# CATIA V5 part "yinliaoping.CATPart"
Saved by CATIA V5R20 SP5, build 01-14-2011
Part number: 饮料瓶
Material "DS Light Blue": density 7860 kg/m3, Young's modulus 2e+11 Pa, Poisson ratio 0.266
Bounding box of the stored display mesh (mm): x -25.2 to 25, y -25 to 25, z 0 to 110
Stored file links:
  E:\180211226\yinliaoping.CATPart
  C:\Program Files\Dassault Systemes\B20\intel_a\startup\materials\Catalog.CATMaterial
  C:\Program Files\Dassault Systemes\B20\intel_a\startup\materials\blue_env_512x512.jpg
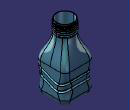
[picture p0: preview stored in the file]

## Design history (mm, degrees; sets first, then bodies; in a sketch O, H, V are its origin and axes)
Set1
  Sketch1 on xy-plane, origin (0, 0, 0), H (1, 0, 0), V (0, 1, 0)
    line L1 (25, 25) -> (25, -25)
    line L2 (25, -25) -> (-25, -25)
    line L3 (-25, -25) -> (-25, 25)
    line L4 (-25, 25) -> (25, 25)
    length L4 = 50
    length L1 = 50
    vertical: L1 V, L3 V
    horizontal: L2 H, L4 H
    equidistance: L1 L3 O, L2 L4 O
  Sketch2 on face of Pad1 from Sketch1.L1, origin (25, 0, 0), H (0, 1, 0), V (0, 0, 1)
    spline S1 through (-40, 20) (-20, 30) (10, 20) (30, 30)
  Extrude1: Element1 Sketch2, Lim1 70, Lim2 0
  MultiSel1: CommonCtxFeats ({extract ExtractElem face of Pad1 from Sketch1.L2}; {extract ExtractElem face of Fillet1}; {extract ExtractElem face of Pad1 from Sketch1.L1}; {extract ExtractElem face of Fillet1}; {extract ExtractElem face of Pad1 from Sketch1.L4}; {extract ExtractElem face of Fillet1}; {extract ExtractElem face of Pad1 from Sketch1.L3}; {extract ExtractElem face of Fillet1})
  Sketch3 on face of Pad1 from Sketch1.L1, origin (25, 0, 0), H (0, 1, 0), V (0, 0, 1)
    spline S1 through (-40, 30) (-20, 40) (10, 30) (30, 40)
  Extrude2: Element1 Sketch3, Lim1 70, Lim2 0
  MultiSel2: CommonCtxFeats ({extract ExtractElem face of Pad1 from Sketch1.L4}; {extract ExtractElem face of Fillet1}; {extract ExtractElem face of Pad1 from Sketch1.L1}; {extract ExtractElem face of Fillet1}; {extract ExtractElem face of Pad1 from Sketch1.L3}; {extract ExtractElem face of Fillet1}; {extract ExtractElem face of Pad1 from Sketch1.L2}; {extract ExtractElem face of Fillet1})
  Join1: Elements ({intersect ToIntersect1 {extract ExtractElem face of Pad1 from Sketch1.L2}, ToIntersect2 Extrude1}; {intersect ToIntersect1 {extract ExtractElem face of Fillet1}, ToIntersect2 Extrude1}; {intersect ToIntersect1 {extract ExtractElem face of Pad1 from Sketch1.L1}, ToIntersect2 Extrude1}; {intersect ToIntersect1 {extract ExtractElem face of Fillet1}, ToIntersect2 Extrude1}; {intersect ToIntersect1 {extract ExtractElem face of Pad1 from Sketch1.L4}, ToIntersect2 Extrude1}; {intersect ToIntersect1 {extract ExtractElem face of Fillet1}, ToIntersect2 Extrude1}; {intersect ToIntersect1 {extract ExtractElem face of Pad1 from Sketch1.L3}, ToIntersect2 Extrude1}; {intersect ToIntersect1 {extract ExtractElem face of Fillet1}, ToIntersect2 Extrude1})
  Join2: Elements ({intersect ToIntersect1 {extract ExtractElem face of Pad1 from Sketch1.L4}, ToIntersect2 Extrude2}; {intersect ToIntersect1 {extract ExtractElem face of Fillet1}, ToIntersect2 Extrude2}; {intersect ToIntersect1 {extract ExtractElem face of Pad1 from Sketch1.L1}, ToIntersect2 Extrude2}; {intersect ToIntersect1 {extract ExtractElem face of Fillet1}, ToIntersect2 Extrude2}; {intersect ToIntersect1 {extract ExtractElem face of Pad1 from Sketch1.L3}, ToIntersect2 Extrude2}; {intersect ToIntersect1 {extract ExtractElem face of Fillet1}, ToIntersect2 Extrude2}; {intersect ToIntersect1 {extract ExtractElem face of Pad1 from Sketch1.L2}, ToIntersect2 Extrude2}; {intersect ToIntersect1 {extract ExtractElem face of Fillet1}, ToIntersect2 Extrude2})
  Plane1: type Normal, Curve Join1, RefPoint vertex [face of MultiSel1 | face of MultiSel1]
  Sketch4 on Plane1, origin (0, -20.5956, 7.0712), H (1, 0, 0), V (0, 0.3247, 0.9458)
    circle A1 centre (25.2218, 22.4128) radius 2
    radius A1 = 2
Body1 (main body), material "DS Light Blue"
  Pad1: profile Sketch1, direction (0, 0, 1), length 50
  Fillet1: on edge [face of Pad1 from Sketch1.L2 | face of Pad1 from Sketch1.L3]; edge [face of Pad1 from Sketch1.L1 | face of Pad1 from Sketch1.L2]; edge [face of Pad1 from Sketch1.L3 | face of Pad1 from Sketch1.L4]; edge [face of Pad1 from Sketch1.L4 | face of Pad1 from Sketch1.L1]
  Fillet2: radius 8, on start face of Pad1
  Plane2: type Offset, RefPlane xy-plane, Offset 90
  Sketch5 on Plane2, origin (0, 0, 90), H (1, 0, 0), V (0, 1, 0)
    circle A1 centre (0, 0) radius 15
    radius A1 = 15
  Pad2: profile Sketch5, direction (0, 0, 1), length 20
  Sketch6 on end face of Pad1, origin (0, 0, 50), H (1, 0, 0), V (0, 1, 0)
    point P1 (25, 0)
    distance P1 V = 25
    coincidence: P1 H
  Sketch7 on start face of Pad2, origin (0, 0, 90), H (1, 0, 0), V (0, -1, 0)
    point P1 (15, 0)
    distance P1 V = 15
    coincidence: P1 H
  Loft1: solid, Sections ({boundary Boundary {extract ExtractElem start face of Pad2}}; {boundary Boundary {extract ExtractElem end face of Pad1}}), StartFace start face of Pad2, EndFace end face of Pad1
  Slot1: profile Sketch4, centre curve Join1
  Plane3: type Normal, Curve Join2, RefPoint vertex [face of MultiSel2 | face of MultiSel2]
  Sketch8 on Plane3, origin (0, -24.5459, 6.218), H (1, 0, 0), V (0, 0.2456, 0.9694)
    circle A1 centre (24.9098, 34.4051) radius 2
    radius A1 = 2
  Slot2: profile Sketch8, centre curve Join2
  Shell1: ExtOffset 0, Face end face of Pad2, IntOffset 1
  Plane4: type Offset, RefPlane Plane2, Offset 2
  Sketch9 on Plane4, origin (0, 0, 92), H (1, 0, 0), V (0, 1, 0)
    point P1 (15, 0)
    distance P1 V = 15
    coincidence: P1 H
  Helix1: Direction Z axis, RefPoint Sketch9, Pitch 3, Height 16, TaperAngle 0
  Point1: type OnCurve, Support Helix1, Length 5
  Line1: type PtDir, RefPoint Sketch9, Direction (1, 0, 0), Start 0, End 5
  Connect1: Curve1 Line1, Point1 vertex of Line1, Tension1 1, Curve2 Helix1, Point2 Point1, Tension2 1
  Point2: type OnCurve, Support Connect1, RefPoint vertex of Helix1, Length 5
  Line2: type PtDir, RefPoint vertex of Helix1, Direction (0, 1, 0), Start 0, End 5
  Connect2: Curve1 Connect1, Point1 Point2, Tension1 1, Curve2 Line2, Point2 vertex of Line2, Tension2 1
  Plane5: type Normal, Curve Connect2
  Sketch10 on Plane5, origin (2.8332, -1.4456, 0.1012), H (0.4545, 0.8908, 0), V (-0.0283, 0.0145, 0.9995)
    circle A1 centre (-14.7535, 100.0233) radius 1
    radius A1 = 1
  Rib1: profile Sketch10, centre curve Connect2
  Body2
    Sketch11 on Plane2, origin (0, 0, 90), H (1, 0, 0), V (0, 1, 0)
      circle A1 centre (0, 0) radius 14
      radius A1 = 14
    Pad3: profile Sketch11, direction (0, 0, 1), length 20
  Remove1: tool Body2
Body3
Body4
  Sketch12 on face of Pad1 from Sketch1.L3, origin (-25, 0, 0), H (0, -1, 0), V (0, 0, 1)
    polyline C1
    polyline C2
    polyline C3
    polyline C4
    polyline C5
    polyline C6
    polyline C7
    polyline C8
    polyline C9
    polyline C10
    polyline C11
  Pad4: profile Sketch12, direction (-1, 0, 0), length 0.2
